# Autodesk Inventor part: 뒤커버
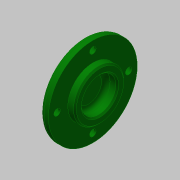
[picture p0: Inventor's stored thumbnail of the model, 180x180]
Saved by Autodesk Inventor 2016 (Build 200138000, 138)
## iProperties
Created: 2015-12
Part Number: 뒤커버
Document SubType Name: Modeling
Designer: mdu
Density: 2.71 g/cm^3
Material: 알루미늄 6061
Appearance: 진녹색
Mass: 56.1995 g
Surface Area: 84.0425 cm^2
Volume: 20.7378 cm^3
Author: mdu
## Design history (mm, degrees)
sketch "스케치1"
  geometry: L1 (-7, 0)-(7, 0); L2 (-7, 0)-(-7, 15.539); L3 (-7, 15.539)-(-4, 18.5); L4 (-4, 18.5)-(-4, 31); L5 (-4, 31)-(2, 31); L6 (2, 31)-(2, 17.5); L7 (2, 17.5)-(7, 17.5); L8 (7, 17.5)-(7, 0); 2 further points
  constraints: 16 end point, 4 parallel, 2 perpendicular, 1 coincident, 1 horizontal, 1 midpoint
  dimensions: "d0" = 14 distance of L1.start L1.end; "d1" = 62 diameter of L5 L1; "d2" = 35 diameter of L7 L1; "d3" = 37 diameter of L3.end L1; "d4" = 3 distance between parallel lines of L4 L2; "d5" = 6 distance of L4.end L5.end
revolve "회전1" sketch "스케치1" stored, may be unused: angle "d6" = 90 deg
sketch "스케치2" dims "d32" = 50
  geometry: 3 further points
  constraints: 2 vertical alignment, 1 coincident, 2 other
hole "구멍1" sketch "스케치2" at (0, 25) diameter "d8" = 4.5; stored, may be unused: countersink angle "d12" = 90 deg, drill point angle "d14" = 118 deg; dims "d9" = 6, "d10" = 8, "d11" = 4.4, "d13" = 8
hole "구멍2" diameter "d20" = 24; stored, may be unused: countersink angle "d24" = 90 deg, drill point angle "d26" = 0 deg; dims "d18" = 10, "d19" = 10, "d21" = 6, "d22" = 8, "d23" = 4.4, "d25" = 8
fillet "모깎기1" dims "d27" = 3
fillet "모깎기2" dims "d28" = 3
chamfer "모따기1" distance "d29" = 1; stored, may be unused: second distance "d30" = 2, angle "d31" = 45 deg
node "솔리드1"
pattern_circular "원형 패턴1" dims angle "d16" = 360 deg
